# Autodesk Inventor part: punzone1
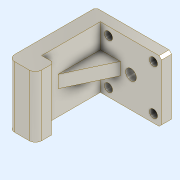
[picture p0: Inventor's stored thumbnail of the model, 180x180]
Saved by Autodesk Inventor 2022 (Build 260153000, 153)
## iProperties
Created: 2022-01
Part Number: punzone1
Material: Generico
Document SubType Name: Modeling
Designer: admin
Density: 1 g/cm^3
Appearance: Titanio - Lucidato
Author: admin
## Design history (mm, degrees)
sketch "Schizzo1"
  geometry: L1 (23.086, 24.5)-(24.5, 23.086) reference; L2 (-23.086, 24.5)-(23.086, 24.5) reference; L3 (-24.5, 23.086)-(-23.086, 24.5) reference; L4 (-24.5, -23.086)-(-24.5, 23.086) reference; L5 (-23.086, -24.5)-(-24.5, -23.086) reference; L6 (23.086, -24.5)-(-23.086, -24.5) reference; L7 (24.5, -23.086)-(23.086, -24.5) reference; L8 (24.5, 23.086)-(24.5, -23.086) reference; L9 (-24.5, 23.086)-(-24.5, 24.5); L10 (-24.5, 24.5)-(-23.086, 24.5); L11 (-24.5, 24.5)-(24.5, 24.5); L12 (24.5, 24.5)-(24.5, -24.5); L13 (24.5, -24.5)-(-24.5, -24.5); L14 (-24.5, -24.5)-(-24.5, 24.5); C1 r 4.323 at (0, 0) reference; C2 r 3.25 at (-18, -18) reference; C3 r 3.25 at (-18, 18) reference; C4 r 3.25 at (18, -18) reference; C5 r 3.25 at (18, 18) reference; 7 further points
  constraints: 12 end point, 3 perpendicular, 2 parallel, 1 horizontal, 1 point on line
  node "Riferimento1"
node "Piano di lavoro1"
extrude "Estrusione1" new body sketch "Schizzo1" distance "d0" = 8; taper "d1" = 0 deg
sketch "Schizzo4"
  geometry: L1 (24.5, -24.5)-(36.11, -24.5); L2 (36.11, -24.5)-(36.11, 24.5); L3 (36.11, 24.5)-(24.5, 24.5); L4 (24.5, 24.5)-(24.5, -24.5); 1 further point
  constraints: 8 end point, 2 parallel, 1 horizontal, 1 perpendicular
  dimensions: "d4" = 11.61 distance of L1.start L1.end
extrude "Estrusione2" join sketch "Schizzo4" distance "d2" = 70; taper "d3" = 0 deg
chamfer "Smusso1" distance "d5" = 2; stored, may be unused: second distance "d6" = 2, angle "d7" = 45 deg
node "Piano di lavoro2"
sketch "Schizzo5"
  geometry: L1 (-28.823, 8)-(-20.176, 8) reference; L2 (-33, 8)-(-49, 41.851); L3 (-49, 8)-(-49, 70) reference; L4 (-49, 8)-(-49, 41.851); L5 (-49, 8)-(-33, 8); 1 further point
  constraints: 6 end point, 2 point on line, 1 perpendicular, 1 vertical
  dimensions: "d14" = 16 distance of L3.start L2.start
extrude "Estrusione3" join sketch "Schizzo5" stored distance "d8" = 10; taper "d9" = 0 deg
fillet "Raccordo1" dims "d10" = 5
chamfer "Smusso3" distance "d15" = 2; stored, may be unused: second distance "d16" = 2, angle "d17" = 45 deg
sketch "Schizzo6"
  geometry: L1 (62, 49)-(0, 49) reference; L2 (68, 0)-(5, 0) reference; L3 (0, 49)-(15, 49); L4 (15, 49)-(15, 0); L5 (15, 0)-(0, 0); L6 (0, 0)-(0, 49); 3 further points
  constraints: 8 end point, 2 parallel, 1 horizontal, 1 perpendicular, 1 point on line
  dimensions: "d18" = 15 distance of L4.end L5.end
extrude "Estrusione4" join sketch "Schizzo6" distance "d19" = 10; taper "d20" = 0 deg
fillet "Raccordo2" dims "d21" = 5
chamfer "Smusso4" distance "d22" = 2; stored, may be unused: second distance "d23" = 2, angle "d24" = 45 deg
node "Solido1"
